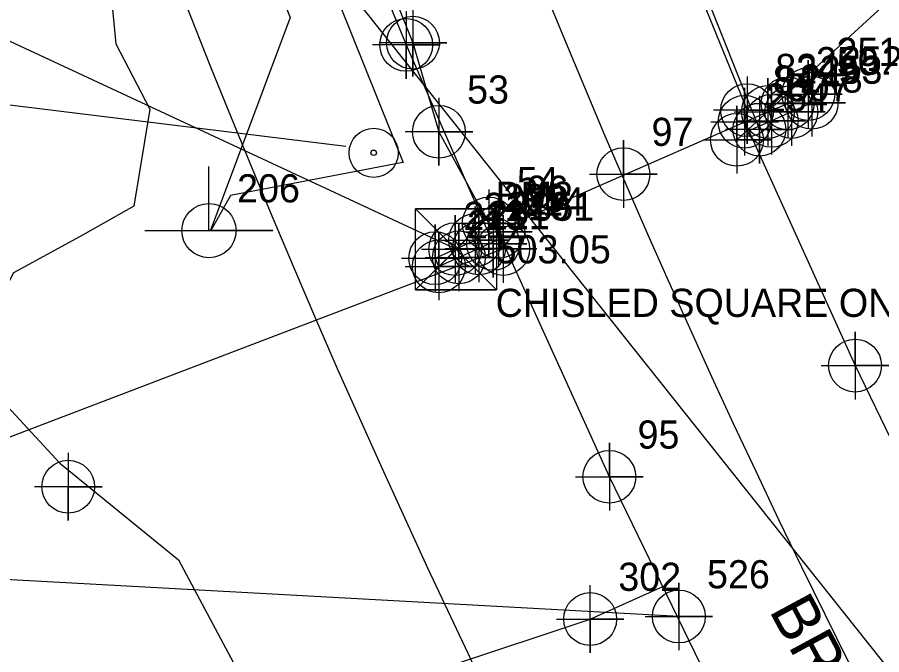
# Model space of a CAD drawing. Extents: x 1534145 to 1537876, y 509021 to 513201.
# Drawn here: x 1536040.8 to 1536117.6, y 511733.6 to 511790.2 of the extents above; entities that cross this region are included whole.
import ezdxf

# ---------------------------------------------------------------- set-up
doc = ezdxf.new("R2010")
doc.units = 0
for name, color, linetype in [('CTL Bench Mark CELL', 7, 'Continuous'), ('CTL Bench Mark Cogo Comment', 7, 'Continuous'), ('CTL Bench Mark Cogo Elevation', 7, 'Continuous'), ('CTL Bench Mark Cogo Number', 7, 'Continuous'), ('CTL Bench Mark Leader', 7, 'Continuous'), ('Default Symbol CELL', 7, 'Continuous'), ('Exist Guardrail', 7, 'Continuous'), ('Exist Guardrail Cogo Number', 7, 'Continuous'), ('Exist Guardrail Cogo Point CELL', 7, 'Continuous'), ('Exist Horizontal Alignment', 7, 'Continuous'), ('Exist Horizontal Baseline Alignment', 7, 'Continuous'), ('Exist Hydro Jurisdictional Stream or Body of Water', 7, 'Continuous'), ('Exist Hydro Stream or Body of Water Cogo Number', 7, 'Continuous'), ('Exist Hydro Stream or Body of Water Cogo Point CELL', 7, 'Continuous'), ('Exist Right of Way Line', 7, 'Continuous'), ('Exist Roads EOP', 7, 'Continuous'), ('Exist Roads EOP Cogo Number', 7, 'Continuous'), ('Exist Roads EOP Cogo Point CELL', 7, 'Continuous'), ('Exist Structure Major Bridge Seat Cogo Number', 7, 'Continuous'), ('Exist Structure Major Bridge Seat Cogo Point CELL', 7, 'Continuous'), ('Exist Structure Major Bridge Seat Top Elevation', 7, 'Continuous'), ('Exist Structure Major Bridge WW', 7, 'Continuous'), ('Exist Structure Major Bridge WW Cogo Number', 7, 'Continuous'), ('Exist Structure Major Bridge WW Cogo Point CELL', 7, 'Continuous'), ('Exist Structure Major Deck Tunnel Box Culvert', 7, 'Continuous'), ('Exist Structure Major Deck Tunnel Box Culvert Cogo Number', 7, 'Continuous'), ('Exist Structure Major Deck Tunnel Box Culvert Cogo Point CELL', 7, 'Continuous'), ('Exist Structure Major Deck Tunnel Box Culvert Text', 7, 'Continuous'), ('Exist Utilities Other Located Object CELL', 7, 'Continuous'), ('Exist Utilities Other Located Object Leader', 7, 'Continuous'), ('Exist Utilities Telephone Joint Use Power CELL', 7, 'Continuous'), ('Exist Utilities Telephone Joint Use Power Cogo Number', 7, 'Continuous'), ('Exist Utilities Telephone UG Cable', 7, 'Continuous'), ('Exist Utilities Telephone UG FO', 7, 'Continuous'), ('Exist Utilities Telephone UG FO SUE', 7, 'Continuous'), ('Exist Vegetation Woods Line', 7, 'Continuous')]:
    doc.layers.add(name, color=color, linetype=linetype)

# ---------------------------------------------------------------- blocks, each defined once
blk = doc.blocks.new('EXIST UTILITIES TELEPHONE JOINT USE POWER')
at = {"layer": 'Exist Utilities Telephone Joint Use Power CELL'}
blk.add_line((0, 0), (0, 0), dxfattribs=at)
blk.add_lwpolyline([(-0.1135, 0), (0.11325, 0), (0, 0), (0, 0.1135)], dxfattribs=at)
blk.add_circle((0, 0), 0.04813, dxfattribs=at)
blk = doc.blocks.new('CTL BENCH MARK')
at = {"layer": 'CTL Bench Mark CELL'}
blk.add_line((0, 0), (0, 0), dxfattribs=at)
blk.add_lwpolyline([(-0.072, 0.07175), (0.07175, 0.07175), (0.07175, -0.072), (-0.072, -0.072)], close=True, dxfattribs=at)
for points in [[(0.07175, 0.07175), (-0.072, -0.072), (-0.000125, -0.000125), (0.07175, -0.072), (-0.072, 0.07175)], [(-0.000125, -0.000125), (0.07175, 0.07175), (-0.072, 0.07175), (-0.000125, -0.000125)], [(-0.000125, -0.000125), (-0.072, -0.072), (0.07175, -0.072), (-0.000125, -0.000125)]]:
    blk.add_lwpolyline(points, dxfattribs=at)
blk = doc.blocks.new('EXIST UTILITIES OTHER LOCATED OBJECT')
at = {"layer": 'Exist Utilities Other Located Object CELL'}
for radius in [0.0436, 0.0048]:
    blk.add_circle((0, 0), radius, dxfattribs=at)

msp = doc.modelspace()

# ---------------------------------------------------------------- linework, layer by layer
at = {"layer": 'CTL Bench Mark Leader'}
msp.add_lwpolyline([(1536079.8, 511769.6), (1536008.416, 511802.86), (1536001.113, 511817.019)], dxfattribs=at)
at = {"layer": 'Default Symbol CELL'}
msp.add_lwpolyline([(1536045.37, 511751.532), (1536045.37, 511745.532), (1536045.37, 511748.532), (1536048.37, 511748.532), (1536042.37, 511748.532)], dxfattribs=at)
msp.add_circle((1536045.37, 511748.532), 2.344, dxfattribs=at)
at = {"layer": 'Exist Guardrail'}
for points in [[(1536074.853, 511872.535), (1536075.971, 511871.123), (1536078.13, 511864.339), (1536081.932, 511850.29), (1536088.139, 511829.732), (1536094.992, 511810.789), (1536101.363, 511793.669), (1536106.713, 511780.223)], [(1536048.092, 511860.888), (1536048.2, 511859.044), (1536054.518, 511840.773), (1536061.186, 511823.13), (1536067.995, 511805.641), (1536075.366, 511787.741), (1536083.083, 511770.087)]]:
    msp.add_lwpolyline(points, dxfattribs=at)
at = {"layer": 'Exist Guardrail Cogo Point CELL'}
for points in [[(1536075.366, 511790.741), (1536075.366, 511784.741), (1536075.366, 511787.741), (1536078.366, 511787.741), (1536072.366, 511787.741)], [(1536106.713, 511783.223), (1536106.713, 511777.223), (1536106.713, 511780.223), (1536109.713, 511780.223), (1536103.713, 511780.223)], [(1536083.083, 511773.087), (1536083.083, 511767.087), (1536083.083, 511770.087), (1536086.083, 511770.087), (1536080.083, 511770.087)]]:
    msp.add_lwpolyline(points, dxfattribs=at)
for centre in [(1536075.366, 511787.741), (1536106.713, 511780.223), (1536083.083, 511770.087)]:
    msp.add_circle(centre, 2.344, dxfattribs=at)
at = {"layer": 'Exist Horizontal Alignment'}
msp.add_arc((1536874.855, 512113.154), 850, 183.46397, 223.994403, dxfattribs=at)
at = {"layer": 'Exist Horizontal Baseline Alignment'}
msp.add_line((1536066.279, 511797.596), (1536449.441, 511315.8), dxfattribs=at)
at = {"layer": 'Exist Hydro Jurisdictional Stream or Body of Water'}
msp.add_lwpolyline([(1535860.327, 511701.56), (1535866.305, 511709.523), (1535895.375, 511711.065), (1535941.656, 511715.79), (1535970.226, 511715.453), (1535985.702, 511698.72), (1536029.159, 511711.807), (1536025.187, 511721.141), (1536041.992, 511721.748), (1536066.515, 511728.418), (1536091.691, 511736.788), (1536098.137, 511739.661)], dxfattribs=at)
at = {"layer": 'Exist Hydro Stream or Body of Water Cogo Point CELL'}
msp.add_lwpolyline([(1536088.691, 511736.788), (1536094.691, 511736.788), (1536091.691, 511736.788), (1536091.691, 511733.788), (1536091.691, 511739.788)], dxfattribs=at)
msp.add_circle((1536091.691, 511736.788), 2.344, dxfattribs=at)
at = {"layer": 'Exist Right of Way Line'}
for radius, end in [(820, 207.242925), (880, 223.994403)]:
    msp.add_arc((1536874.855, 512113.154), radius, 183.46397, end, dxfattribs=at)
at = {"layer": 'Exist Roads EOP'}
for points in [[(1536017.127, 512355.263), (1536014.258, 512300.49), (1536012.138, 512243.655), (1536010.766, 512187.002), (1536010.935, 512130.319), (1536011.885, 512103.447), (1536013.151, 512076.442), (1536015.189, 512049.652), (1536017.801, 512022.412), (1536021.134, 511995.466), (1536025.003, 511968.91), (1536024.581, 511966.831), (1536029.206, 511941.046), (1536034.764, 511914.701), (1536041.437, 511889.37), (1536049.315, 511861.119), (1536057.395, 511835.942), (1536066.823, 511810.745), (1536075.962, 511787.935), (1536078.268, 511780.03), (1536082.687, 511771.896), (1536083.544, 511771.142)], [(1536047.727, 511997.734), (1536051.294, 511973.891), (1536055.95, 511946.526), (1536061.193, 511920.283), (1536066.769, 511896.005), (1536074.658, 511868.783), (1536082.438, 511844.103), (1536091.167, 511819.718), (1536099.538, 511796.917), (1536105.626, 511781.946), (1536105.402, 511780.92)]]:
    msp.add_lwpolyline(points, dxfattribs=at)
at = {"layer": 'Exist Roads EOP Cogo Point CELL'}
for points in [[(1536075.962, 511790.935), (1536075.962, 511784.935), (1536075.962, 511787.935), (1536078.962, 511787.935), (1536072.962, 511787.935)], [(1536105.626, 511784.946), (1536105.626, 511778.946), (1536105.626, 511781.946), (1536108.626, 511781.946), (1536102.626, 511781.946)], [(1536078.268, 511783.03), (1536078.268, 511777.03), (1536078.268, 511780.03), (1536081.268, 511780.03), (1536075.268, 511780.03)], [(1536082.687, 511774.896), (1536082.687, 511768.896), (1536082.687, 511771.896), (1536085.687, 511771.896), (1536079.687, 511771.896)]]:
    msp.add_lwpolyline(points, dxfattribs=at)
for centre in [(1536075.962, 511787.935), (1536105.626, 511781.946), (1536078.268, 511780.03), (1536082.687, 511771.896)]:
    msp.add_circle(centre, 2.344, dxfattribs=at)
at = {"layer": 'Exist Structure Major Bridge Seat Cogo Point CELL'}
for points in [[(1536101.719, 511779.32), (1536107.719, 511779.32), (1536104.719, 511779.32), (1536104.719, 511782.32), (1536104.719, 511776.32)], [(1536080.973, 511769.63), (1536086.973, 511769.63), (1536083.973, 511769.63), (1536083.973, 511772.63), (1536083.973, 511766.63)], [(1536096.563, 511737.012), (1536102.563, 511737.012), (1536099.563, 511737.012), (1536099.563, 511740.012), (1536099.563, 511734.012)]]:
    msp.add_lwpolyline(points, dxfattribs=at)
for centre in [(1536104.719, 511779.32), (1536083.973, 511769.63), (1536099.563, 511737.012)]:
    msp.add_circle(centre, 2.344, dxfattribs=at)
at = {"layer": 'Exist Structure Major Bridge Seat Top Elevation'}
for points in [[(1536104.719, 511779.32), (1536145.84, 511816.961), (1536143.09, 511822.293)], [(1536083.973, 511769.63), (1536023.695, 511746.655), (1536020.944, 511751.988)], [(1536099.563, 511737.012), (1536017.121, 511741.553), (1536014.371, 511746.886)]]:
    msp.add_lwpolyline(points, dxfattribs=at)
at = {"layer": 'Exist Structure Major Bridge WW'}
for points in [[(1536107.474, 511781.791), (1536109.224, 511782.547), (1536111.052, 511783.374), (1536111.352, 511782.604), (1536109.552, 511781.79), (1536107.799, 511781.004), (1536105.765, 511780.117)], [(1536083.813, 511770.548), (1536081.823, 511769.681), (1536080.04, 511768.882), (1536078.259, 511768.082), (1536077.942, 511768.815), (1536079.717, 511769.617), (1536081.482, 511770.41), (1536107.474, 511781.791)]]:
    msp.add_lwpolyline(points, dxfattribs=at)
at = {"layer": 'Exist Structure Major Bridge WW Cogo Point CELL'}
for points in [[(1536108.052, 511783.374), (1536114.052, 511783.374), (1536111.052, 511783.374), (1536111.052, 511786.374), (1536111.052, 511780.374)], [(1536108.352, 511782.604), (1536114.352, 511782.604), (1536111.352, 511782.604), (1536111.352, 511785.604), (1536111.352, 511779.604)], [(1536106.224, 511782.547), (1536112.224, 511782.547), (1536109.224, 511782.547), (1536109.224, 511785.547), (1536109.224, 511779.547)], [(1536104.474, 511781.791), (1536110.474, 511781.791), (1536107.474, 511781.791), (1536107.474, 511784.791), (1536107.474, 511778.791)], [(1536106.552, 511781.79), (1536112.552, 511781.79), (1536109.552, 511781.79), (1536109.552, 511784.79), (1536109.552, 511778.79)], [(1536104.799, 511781.004), (1536110.799, 511781.004), (1536107.799, 511781.004), (1536107.799, 511784.004), (1536107.799, 511778.004)], [(1536078.482, 511770.41), (1536084.482, 511770.41), (1536081.482, 511770.41), (1536081.482, 511773.41), (1536081.482, 511767.41)], [(1536076.717, 511769.617), (1536082.717, 511769.617), (1536079.717, 511769.617), (1536079.717, 511772.617), (1536079.717, 511766.617)], [(1536078.823, 511769.681), (1536084.823, 511769.681), (1536081.823, 511769.681), (1536081.823, 511772.681), (1536081.823, 511766.681)], [(1536074.942, 511768.815), (1536080.942, 511768.815), (1536077.942, 511768.815), (1536077.942, 511771.815), (1536077.942, 511765.815)], [(1536077.04, 511768.882), (1536083.04, 511768.882), (1536080.04, 511768.882), (1536080.04, 511771.882), (1536080.04, 511765.882)], [(1536075.259, 511768.082), (1536081.259, 511768.082), (1536078.259, 511768.082), (1536078.259, 511771.082), (1536078.259, 511765.082)]]:
    msp.add_lwpolyline(points, dxfattribs=at)
for centre in [(1536111.052, 511783.374), (1536109.224, 511782.547), (1536111.352, 511782.604), (1536107.474, 511781.791), (1536109.552, 511781.79), (1536107.799, 511781.004), (1536081.482, 511770.41), (1536079.717, 511769.617), (1536081.823, 511769.681), (1536077.942, 511768.815), (1536080.04, 511768.882), (1536078.259, 511768.082)]:
    msp.add_circle(centre, 2.344, dxfattribs=at)
at = {"layer": 'Exist Structure Major Deck Tunnel Box Culvert'}
for points in [[(1536105.415, 511780.89), (1536115.204, 511759.278), (1536125.978, 511737.055), (1536137.115, 511715.805), (1536148.754, 511694.832), (1536156.182, 511682.145)], [(1536135.59, 511669.86), (1536128.436, 511682.142), (1536116.192, 511704.013), (1536104.563, 511726.447), (1536093.394, 511749.412), (1536083.48, 511771.285)]]:
    msp.add_lwpolyline(points, dxfattribs=at)
at = {"layer": 'Exist Structure Major Deck Tunnel Box Culvert Cogo Point CELL'}
for points in [[(1536102.402, 511780.92), (1536108.402, 511780.92), (1536105.402, 511780.92), (1536105.402, 511783.92), (1536105.402, 511777.92)], [(1536091.64, 511776.274), (1536097.64, 511776.274), (1536094.64, 511776.274), (1536094.64, 511779.274), (1536094.64, 511773.274)], [(1536080.544, 511771.142), (1536086.544, 511771.142), (1536083.544, 511771.142), (1536083.544, 511774.142), (1536083.544, 511768.142)], [(1536112.204, 511759.278), (1536118.204, 511759.278), (1536115.204, 511759.278), (1536115.204, 511762.278), (1536115.204, 511756.278)], [(1536090.394, 511749.412), (1536096.394, 511749.412), (1536093.394, 511749.412), (1536093.394, 511752.412), (1536093.394, 511746.412)]]:
    msp.add_lwpolyline(points, dxfattribs=at)
for centre in [(1536105.402, 511780.92), (1536094.64, 511776.274), (1536083.544, 511771.142), (1536115.204, 511759.278), (1536093.394, 511749.412)]:
    msp.add_circle(centre, 2.344, dxfattribs=at)
at = {"layer": 'Exist Utilities Other Located Object Leader'}
msp.add_lwpolyline([(1536070.002, 511778.729), (1536026.204, 511784.102)], dxfattribs=at)
at = {"layer": 'Exist Utilities Telephone UG Cable'}
for points in [[(1536007.514, 512112.188), (1536011.33, 512050.437), (1536011.992, 512042.854), (1536022.088, 511963.64), (1536039.724, 511880.013), (1536042.168, 511848.194), (1536065.07, 511790.175)], [(1536065.07, 511790.175), (1536057.978, 511771.204)]]:
    msp.add_lwpolyline(points, dxfattribs=at)
at = {"layer": 'Exist Utilities Telephone UG FO'}
msp.add_line((1536075.107, 511777.315), (1536075.078, 511777.309), dxfattribs=at)
at = {"layer": 'Exist Utilities Telephone UG FO SUE'}
for p, q in [((1536069.439, 511791.359), (1536075.107, 511777.315)), ((1536075.078, 511777.309), (1536059.762, 511774.381)), ((1536075.107, 511777.315), (1536075.078, 511777.309)), ((1536059.762, 511774.381), (1536057.981, 511771.199))]:
    msp.add_line(p, q, dxfattribs=at)
at = {"layer": 'Exist Vegetation Woods Line'}
for points in [[(1535954.041, 511853.161), (1535966.022, 511858.509), (1535970.596, 511870.907), (1535970.151, 511875.739), (1535974.712, 511881.103), (1535988.59, 511888.028), (1536000.971, 511889.585), (1536009.774, 511882.212), (1536016.62, 511871.882), (1536024.488, 511859.378), (1536025.314, 511851.257), (1536029.328, 511842.498), (1536032.33, 511832.43), (1536038.105, 511823.163), (1536040.702, 511813.198), (1536045.004, 511805.288), (1536048.576, 511798.251), (1536049.606, 511787.843), (1536052.615, 511782.044), (1536051.189, 511773.439), (1536046.439, 511770.727), (1536040.522, 511767.509), (1536036.361, 511759.528)], [(1536036.361, 511759.528), (1536044.624, 511750.628), (1536055.142, 511742.038), (1536060.045, 511732.905), (1536050.945, 511727.969), (1536041.114, 511727.434), (1536031.807, 511731.099), (1536016.968, 511730.12), (1536008.401, 511733.888), (1535991.118, 511734.208)]]:
    msp.add_lwpolyline(points, dxfattribs=at)

# ---------------------------------------------------------------- block references
at = {"layer": 'CTL Bench Mark CELL', "xscale": 50, "yscale": 50}
msp.add_blockref('CTL BENCH MARK', (1536079.8, 511769.6), dxfattribs=at)
at = {"layer": 'Exist Utilities Other Located Object CELL', "xscale": 50, "yscale": 50}
msp.add_blockref('EXIST UTILITIES OTHER LOCATED OBJECT', (1536072.478, 511778.166), dxfattribs=at)
at = {"layer": 'Exist Utilities Telephone Joint Use Power CELL', "xscale": 50, "yscale": 50}
msp.add_blockref('EXIST UTILITIES TELEPHONE JOINT USE POWER', (1536057.856, 511771.26), dxfattribs=at)

# ---------------------------------------------------------------- texts
at = {"layer": 'CTL Bench Mark Cogo Comment'}
msp.add_text('CHISLED SQUARE ON NW SIDE OF BRIDGE WING WALL', height=2.5, dxfattribs=at).set_placement((1536083.3, 511763.6))
at = {"layer": 'CTL Bench Mark Cogo Elevation'}
msp.add_text('503.05', height=2.5, dxfattribs=at).set_placement((1536083.3, 511768.35))
at = {"layer": 'CTL Bench Mark Cogo Number'}
msp.add_text('BM2', height=2.5, dxfattribs=at).set_placement((1536083.3, 511773.1))
at = {"layer": 'Exist Guardrail Cogo Number'}
for s, p in [('507', (1536109.213, 511782.723)), ('514', (1536085.583, 511772.588))]:
    msp.add_text(s, height=2.5, dxfattribs=at).set_placement(p)
at = {"layer": 'Exist Hydro Stream or Body of Water Cogo Number'}
msp.add_text('302', height=2.5, dxfattribs=at).set_placement((1536094.191, 511739.288))
at = {"layer": 'Exist Roads EOP Cogo Number'}
for s, p in [('83', (1536108.126, 511784.446)), ('53', (1536080.768, 511782.53)), ('54', (1536085.187, 511774.396))]:
    msp.add_text(s, height=2.5, dxfattribs=at).set_placement(p)
at = {"layer": 'Exist Structure Major Bridge Seat Cogo Number'}
for s, p in [('254', (1536107.219, 511781.82)), ('351', (1536086.473, 511772.13)), ('526', (1536102.063, 511739.512))]:
    msp.add_text(s, height=2.5, dxfattribs=at).set_placement(p)
at = {"layer": 'Exist Structure Major Bridge WW Cogo Number'}
for s, p in [('251', (1536113.552, 511785.874)), ('250', (1536111.724, 511785.047)), ('252', (1536113.852, 511785.104)), ('249', (1536109.974, 511784.291)), ('253', (1536112.052, 511784.29)), ('248', (1536110.299, 511783.504)), ('209', (1536083.982, 511772.91)), ('214', (1536082.217, 511772.117)), ('210', (1536084.323, 511772.181)), ('213', (1536080.442, 511771.315)), ('211', (1536082.54, 511771.382)), ('212', (1536080.759, 511770.582))]:
    msp.add_text(s, height=2.5, dxfattribs=at).set_placement(p)
at = {"layer": 'Exist Structure Major Deck Tunnel Box Culvert Cogo Number'}
for s, p in [('84', (1536107.902, 511783.42)), ('97', (1536097.14, 511778.774)), ('96', (1536086.044, 511773.642)), ('95', (1536095.894, 511751.912))]:
    msp.add_text(s, height=2.5, dxfattribs=at).set_placement(p)
at = {"layer": 'Exist Structure Major Deck Tunnel Box Culvert Text'}
msp.add_text('BRIDGE #29', height=4, rotation=298.36907, dxfattribs=at).set_placement((1536107.53, 511737.552))
at = {"layer": 'Exist Utilities Telephone Joint Use Power Cogo Number'}
msp.add_text('206', height=2.5, dxfattribs=at).set_placement((1536060.356, 511773.76))

doc.saveas('drawing.dxf')
